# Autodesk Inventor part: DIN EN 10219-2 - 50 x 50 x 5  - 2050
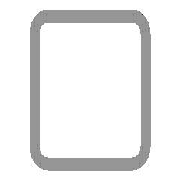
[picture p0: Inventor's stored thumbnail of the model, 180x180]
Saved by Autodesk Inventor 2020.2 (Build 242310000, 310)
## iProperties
Created: 2019-01
Part Number: DIN EN 10219-2 - 50 x 50 x 5  - 2050
Material: Stahl, weich
Description: Kaltgeformte, geschweißte Baustahl-Hohlprofile aus unlegiertem Feinkorn-Baustahl
Document SubType Name: Modeling
Standard: DIN
Designer: lutzd
Standard Revision: 2006-07
Standards Organization: DIN
Language: de-DE
Size Designation: 50 x 50 x 5
Categories: <MemberInstance><Categories><Category DisplayName="Profile" InternalName="089c4875-fa83-4c05-b084-43b9cc11f5ed" Mnemonic="GRDR"><CategoryParameter DisplayName="
Stock Number: 50 x 50 x 5
Mass: 13436.3 g
Surface Area: 6871.59 cm^2
Volume: 1711.63 cm^3
Density: 7.85 g/cm^3
Appearance: Semi-Polished(8)
_CCFamilyMember: 16
_CCFamilyDisplayName: DIN EN 10219-2 (Quadratisches Hohlprofil - Kaltgeformt) - Kaltgeformte, geschweißte Baustahl-Hohlprofile aus unlegiertem Feinkorn-Baustahl
_FrameMemberDoc: Frame Member File
_Version: 15.0.0
_GetPNFromCC: 1
G_W: 50,000 mm
G_H: 50,000 mm
G_L: 2050,000 mm
DocNumber: ADSK-014384
Folder: .
Mass: 13,436 kg
VLT_Material: Stahl, weich
+961D2C3C-FD86-4CD1-A724-55AE8CEB09FC+SCHNITTDETAIL1: Schnittwinkel 90,00 grd
+D6C7C21E-11FC-43CE-93E9-6B47DD219F08+SCHNITTDETAIL2: Schnittwinkel 90,00 grd
Dimensions: 50x50x2050 mm
IsCustomPart: 1
Title: Profil-Bauteil
Author: lutzd
Revision Number: -
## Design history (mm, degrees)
node "Startebene"
node "Endebene"
sketch "Skizze"
  geometry: L1 (-25, -15)-(-25, 15); L2 (-15, 25)-(15, 25); L3 (25, 15)-(25, -15); L4 (15, -25)-(-15, -25); L5 (-15, 20)-(15, 20); L6 (20, 15)-(20, -15); L7 (15, -20)-(-15, -20); L8 (-20, -15)-(-20, 15); L9 (0, 37.899)-(0, -37.899) reference; L10 (-37.899, 0)-(37.899, 0) reference; A1 r 10 centre (-15, -15) between (-25, -15) and (-15, -25); A2 r 10 centre (-15, 15) between (-15, 25) and (-25, 15); A3 r 10 centre (15, 15) between (25, 15) and (15, 25); A4 r 10 centre (15, -15) between (15, -25) and (25, -15); A5 r 5 centre (-15, 15) between (-15, 20) and (-20, 15); A6 r 5 centre (15, 15) between (20, 15) and (15, 20); A7 r 5 centre (15, -15) between (15, -20) and (20, -15); A8 r 5 centre (-15, -15) between (-20, -15) and (-15, -20)
  constraints: 16 end point, 16 point on circle, 8 centre point, 8 tangent, 4 parallel, 3 equal radius, 2 perpendicular, 7 other
  dimensions: "d7" = 10 radius of A1 (= G_IR); "d10" = 50 distance between parallel lines of L2 L4 (= G_H); "d11" = 50 distance between parallel lines of L1 L3 (= G_W); "d12" = 5 distance between parallel lines of L3 L6 (= G_T); "d15" = 25 distance between parallel lines of L2 L10 (= 0.5 x d10); "d16" = 25 distance between parallel lines of L9 L3 (= 0.5 x d11)
extrude "Körper" new body sketch "Skizze" stored distance "d3" = 2050 (= G_L); taper "d4" = 0 deg
node "Driven Length"
  sketch "Sketch3"
    geometry: L1 (0, 0)-(10, 0) reference
    constraints: 2 end point, 1 horizontal
  workplane "Work Plane3"
  sketch "Sketch4"
    geometry: L1 (-2, 60)-(12, 60) reference; L2 (-2, 2110)-(12, 2110) reference
    dimensions: "d18" = 2050 distance between parallel lines of L1 L2 (derived)
workplane "Arbeitsebene4"
feature "Trennen1"
workplane "Arbeitsebene5"
feature "Trennen2"
sketch "Skizze5"
  geometry: L1 (2050, -30)-(2050, 0) reference; 11 further points; 1 other entity
  constraints: 1 coincident, 1 midpoint, 10 other
  dimensions: "d19" = 52 distance of point (1643, -15) point (1695, -15); "d20" = 52 distance of point (1484, -15) point (1536, -15) (= d19); "d21" = 52 distance of point (653, -15) point (705, -15) (= d19); "d22" = 52 distance of point (494, -15) point (546, -15) (= d19); "d23" = 355 distance from line of L1 point (1695, -15); "d24" = 159 distance of point (1536, -15) point (1695, -15); "d25" = 159 distance of point (546, -15) point (705, -15) (= d24); "d26" = 990 distance of point (705, -15) point (1695, -15)
hole "Bohrung1" sketch "Skizze5" at (494, -15), (546, -15), (653, -15), (705, -15), (1484, -15), (1536, -15), (1695, -15), (1643, -15) diameter "d27" = 6.647; stored, may be unused: countersink angle "d31" = 90 deg, drill point angle "d33" = 118 deg; dims "d28" = 16, "d29" = 4, "d30" = 2, "d32" = 8
body "Solid1"
other parameters: "G_W" = 50 [user parameter; used in 1 equation term], "G_H" = 50 [user parameter; used in 1 equation term], "G_T" = 5 [user parameter; used in 1 equation term], "G_IR" = 10 [user parameter; used in 1 equation term], "G_L" = 2050 (= d18) [user parameter; used in 1 equation term], "d17" = 90 deg
